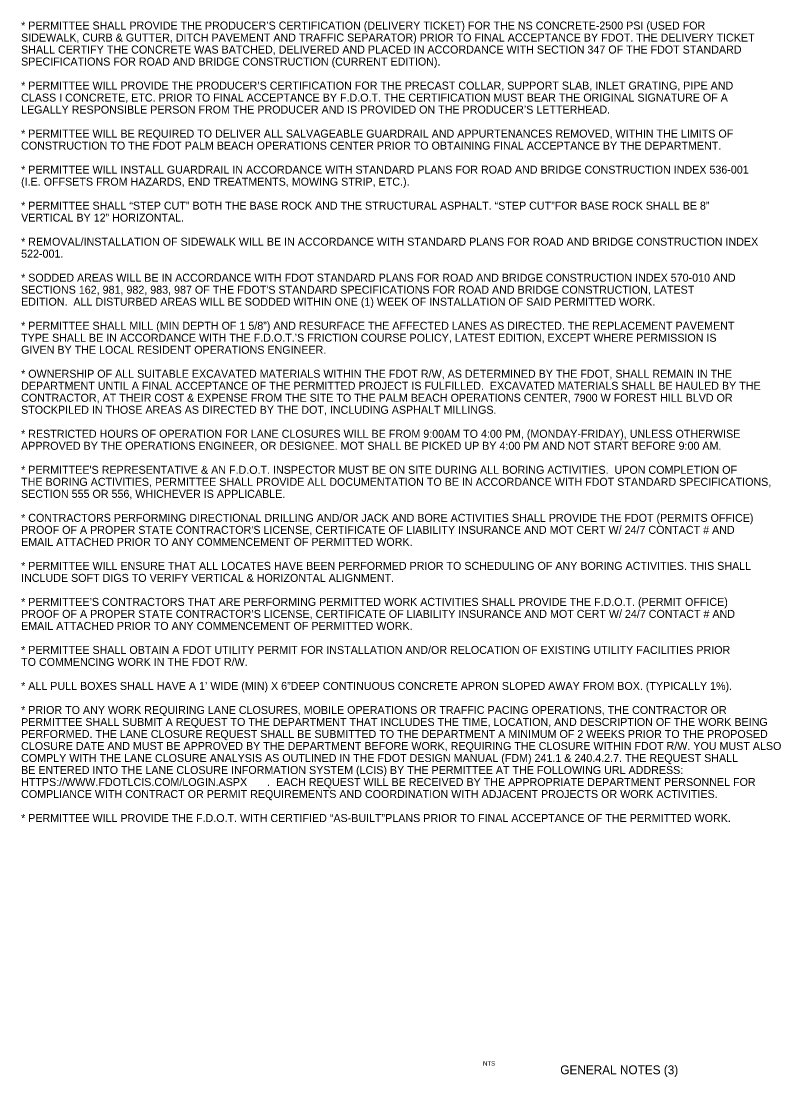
# Model space of a CAD drawing. Extents: x -1.6 to 33.4, y -12.7 to 10.9.
# Drawn here: x 7.75 to 14.39, y -12.34 to -3.11 of the extents above; entities that cross this region are included whole.
import ezdxf

# ---------------------------------------------------------------- set-up
doc = ezdxf.new("R2010")
doc.units = 0
doc.layers.add('NonPlottingEle_dp', color=7, linetype='Continuous')

msp = doc.modelspace()

# ---------------------------------------------------------------- texts
at = {"layer": 'NonPlottingEle_dp'}
for s, height, p in [('* PERMITTEE SHALL PROVIDE THE PRODUCER’S CERTIFICATION (DELIVERY TICKET) FOR THE NS CONCRETE-2500 PSI (USED FOR ', 0.07, (7.746, -3.1818)), ('SIDEWALK, CURB & GUTTER, DITCH PAVEMENT AND TRAFFIC SEPARATOR) PRIOR TO FINAL ACCEPTANCE BY FDOT. THE DELIVERY TICKET ', 0.07, (7.746, -3.2868)), ('SHALL CERTIFY THE CONCRETE WAS BATCHED, DELIVERED AND PLACED IN ACCORDANCE WITH SECTION 347 OF THE FDOT STANDARD ', 0.07, (7.746, -3.3918)), ('SPECIFICATIONS FOR ROAD AND BRIDGE CONSTRUCTION (CURRENT EDITION).', 0.07, (7.746, -3.4968)), ('* PERMITTEE WILL PROVIDE THE PRODUCER’S CERTIFICATION FOR THE PRECAST COLLAR, SUPPORT SLAB, INLET GRATING, PIPE AND ', 0.07, (7.746, -3.7068)), ('CLASS I CONCRETE, ETC. PRIOR TO FINAL ACCEPTANCE BY F.D.O.T. THE CERTIFICATION MUST BEAR THE ORIGINAL SIGNATURE OF A ', 0.07, (7.746, -3.8118)), ('LEGALLY RESPONSIBLE PERSON FROM THE PRODUCER AND IS PROVIDED ON THE PRODUCER’S LETTERHEAD.', 0.07, (7.746, -3.9168)), ('* PERMITTEE WILL BE REQUIRED TO DELIVER ALL SALVAGEABLE GUARDRAIL AND APPURTENANCES REMOVED, WITHIN THE LIMITS OF ', 0.07, (7.746, -4.1268)), ('CONSTRUCTION TO THE FDOT PALM BEACH OPERATIONS CENTER PRIOR TO OBTAINING FINAL ACCEPTANCE BY THE DEPARTMENT.', 0.07, (7.746, -4.2318)), ('* PERMITTEE WILL INSTALL GUARDRAIL IN ACCORDANCE WITH STANDARD PLANS FOR ROAD AND BRIDGE CONSTRUCTION INDEX 536-001 ', 0.07, (7.746, -4.4418)), ('(I.E. OFFSETS FROM HAZARDS, END TREATMENTS, MOWING STRIP, ETC.).', 0.07, (7.746, -4.5468)), ('* PERMITTEE SHALL “STEP CUT” BOTH THE BASE ROCK AND THE STRUCTURAL ASPHALT. “STEP CUT”FOR BASE ROCK SHALL BE 8” ', 0.07, (7.746, -4.7568)), ('VERTICAL BY 12” HORIZONTAL.', 0.07, (7.746, -4.8618)), ('* REMOVAL/INSTALLATION OF SIDEWALK WILL BE IN ACCORDANCE WITH STANDARD PLANS FOR ROAD AND BRIDGE CONSTRUCTION INDEX ', 0.07, (7.746, -5.0718)), ('522-001.', 0.07, (7.746, -5.1768)), ('* SODDED AREAS WILL BE IN ACCORDANCE WITH FDOT STANDARD PLANS FOR ROAD AND BRIDGE CONSTRUCTION INDEX 570-010 AND ', 0.07, (7.746, -5.3868)), ("SECTIONS 162, 981, 982, 983, 987 OF THE FDOT'S STANDARD SPECIFICATIONS FOR ROAD AND BRIDGE CONSTRUCTION, LATEST ", 0.07, (7.746, -5.4918)), ('EDITION.  ALL DISTURBED AREAS WILL BE SODDED WITHIN ONE (1) WEEK OF INSTALLATION OF SAID PERMITTED WORK.', 0.07, (7.746, -5.5968)), ('* PERMITTEE SHALL MILL (MIN DEPTH OF 1 5/8”) AND RESURFACE THE AFFECTED LANES AS DIRECTED. THE REPLACEMENT PAVEMENT ', 0.07, (7.746, -5.8068)), ('TYPE SHALL BE IN ACCORDANCE WITH THE F.D.O.T.’S FRICTION COURSE POLICY, LATEST EDITION, EXCEPT WHERE PERMISSION IS ', 0.07, (7.746, -5.9118)), ('GIVEN BY THE LOCAL RESIDENT OPERATIONS ENGINEER.', 0.07, (7.746, -6.0168)), ('* OWNERSHIP OF ALL SUITABLE EXCAVATED MATERIALS WITHIN THE FDOT R/W, AS DETERMINED BY THE FDOT, SHALL REMAIN IN THE ', 0.07, (7.746, -6.2268)), ('DEPARTMENT UNTIL A FINAL ACCEPTANCE OF THE PERMITTED PROJECT IS FULFILLED.  EXCAVATED MATERIALS SHALL BE HAULED BY THE ', 0.07, (7.746, -6.3318)), ('CONTRACTOR, AT THEIR COST & EXPENSE FROM THE SITE TO THE PALM BEACH OPERATIONS CENTER, 7900 W FOREST HILL BLVD OR ', 0.07, (7.746, -6.4368)), ('STOCKPILED IN THOSE AREAS AS DIRECTED BY THE DOT, INCLUDING ASPHALT MILLINGS.', 0.07, (7.746, -6.5418)), ('* RESTRICTED HOURS OF OPERATION FOR LANE CLOSURES WILL BE FROM 9:00AM TO 4:00 PM, (MONDAY-FRIDAY), UNLESS OTHERWISE ', 0.07, (7.746, -6.7518)), ('APPROVED BY THE OPERATIONS ENGINEER, OR DESIGNEE. MOT SHALL BE PICKED UP BY 4:00 PM AND NOT START BEFORE 9:00 AM.', 0.07, (7.746, -6.8568)), ("* PERMITTEE'S REPRESENTATIVE & AN F.D.O.T. INSPECTOR MUST BE ON SITE DURING ALL BORING ACTIVITIES.  UPON COMPLETION OF ", 0.07, (7.746, -7.0668)), ('THE BORING ACTIVITIES, PERMITTEE SHALL PROVIDE ALL DOCUMENTATION TO BE IN ACCORDANCE WITH FDOT STANDARD SPECIFICATIONS, ', 0.07, (7.746, -7.1718)), ('SECTION 555 OR 556, WHICHEVER IS APPLICABLE.', 0.07, (7.746, -7.2768)), ('* CONTRACTORS PERFORMING DIRECTIONAL DRILLING AND/OR JACK AND BORE ACTIVITIES SHALL PROVIDE THE FDOT (PERMITS OFFICE) ', 0.07, (7.746, -7.4868)), ("PROOF OF A PROPER STATE CONTRACTOR'S LICENSE, CERTIFICATE OF LIABILITY INSURANCE AND MOT CERT W/ 24/7 CONTACT # AND ", 0.07, (7.746, -7.5918)), ('EMAIL ATTACHED PRIOR TO ANY COMMENCEMENT OF PERMITTED WORK.', 0.07, (7.746, -7.6968)), ('* PERMITTEE WILL ENSURE THAT ALL LOCATES HAVE BEEN PERFORMED PRIOR TO SCHEDULING OF ANY BORING ACTIVITIES. THIS SHALL ', 0.07, (7.746, -7.9068)), ('INCLUDE SOFT DIGS TO VERIFY VERTICAL & HORIZONTAL ALIGNMENT.', 0.07, (7.746, -8.0118)), ('* PERMITTEE’S CONTRACTORS THAT ARE PERFORMING PERMITTED WORK ACTIVITIES SHALL PROVIDE THE F.D.O.T. (PERMIT OFFICE) ', 0.07, (7.746, -8.2218)), ('PROOF OF A PROPER STATE CONTRACTOR’S LICENSE, CERTIFICATE OF LIABILITY INSURANCE AND MOT CERT W/ 24/7 CONTACT # AND ', 0.07, (7.746, -8.3268)), ('EMAIL ATTACHED PRIOR TO ANY COMMENCEMENT OF PERMITTED WORK.', 0.07, (7.746, -8.4318)), ('* PERMITTEE SHALL OBTAIN A FDOT UTILITY PERMIT FOR INSTALLATION AND/OR RELOCATION OF EXISTING UTILITY FACILITIES PRIOR ', 0.07, (7.746, -8.6418)), ('TO COMMENCING WORK IN THE FDOT R/W.', 0.07, (7.746, -8.7468)), ('* ALL PULL BOXES SHALL HAVE A 1’ WIDE (MIN) X 6”DEEP CONTINUOUS CONCRETE APRON SLOPED AWAY FROM BOX. (TYPICALLY 1%).', 0.07, (7.746, -8.9568)), ('* PRIOR TO ANY WORK REQUIRING LANE CLOSURES, MOBILE OPERATIONS OR TRAFFIC PACING OPERATIONS, THE CONTRACTOR OR ', 0.07, (7.746, -9.1668)), ('PERMITTEE SHALL SUBMIT A REQUEST TO THE DEPARTMENT THAT INCLUDES THE TIME, LOCATION, AND DESCRIPTION OF THE WORK BEING ', 0.07, (7.746, -9.2718)), ('PERFORMED. THE LANE CLOSURE REQUEST SHALL BE SUBMITTED TO THE DEPARTMENT A MINIMUM OF 2 WEEKS PRIOR TO THE PROPOSED ', 0.07, (7.746, -9.3768)), ('CLOSURE DATE AND MUST BE APPROVED BY THE DEPARTMENT BEFORE WORK, REQUIRING THE CLOSURE WITHIN FDOT R/W. YOU MUST ALSO ', 0.07, (7.746, -9.4818)), ('COMPLY WITH THE LANE CLOSURE ANALYSIS AS OUTLINED IN THE FDOT DESIGN MANUAL (FDM) 241.1 & 240.4.2.7. THE REQUEST SHALL ', 0.07, (7.746, -9.5868)), ('BE ENTERED INTO THE LANE CLOSURE INFORMATION SYSTEM (LCIS) BY THE PERMITTEE AT THE FOLLOWING URL ADDRESS: ', 0.07, (7.746, -9.6918)), ('HTTPS://WWW.FDOTLCIS.COM/LOGIN.ASPX', 0.07, (7.746, -9.7968)), ('.  EACH REQUEST WILL BE RECEIVED BY THE APPROPRIATE DEPARTMENT PERSONNEL FOR ', 0.07, (9.8971, -9.7968)), ('COMPLIANCE WITH CONTRACT OR PERMIT REQUIREMENTS AND COORDINATION WITH ADJACENT PROJECTS OR WORK ACTIVITIES.', 0.07, (7.746, -9.9018)), ('* PERMITTEE WILL PROVIDE THE F.D.O.T. WITH CERTIFIED “AS-BUILT”PLANS PRIOR TO FINAL ACCEPTANCE OF THE PERMITTED WORK.', 0.07, (7.746, -10.1118)), ('NTS', 0.03855, (11.7839, -12.2418)), ('   GENERAL NOTES (3)    ', 0.077091, (12.3737, -12.3172))]:
    msp.add_text(s, height=height, dxfattribs=at).set_placement(p)

doc.saveas('drawing.dxf')
